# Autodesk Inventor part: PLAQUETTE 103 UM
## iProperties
Shininess: 41.0
Angle Display Precision: 2
Document Length Units: 11269
Document Angle Units: 11279
Document Time Units: 11290
Document Mass Units: 11283
Document Length Units Precision: 3
Document Angle Units Precision: 2
Part Number: PLAQUETTE 103 UM
Material: Par défaut
Document SubType Name: Modeling
Density: 0.0
Volumn: 0.0
Area: 0.0
PropertySet Name: Model Information
Control State: 0
Master: False
Checked Out: False
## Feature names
1. Extrusion1
